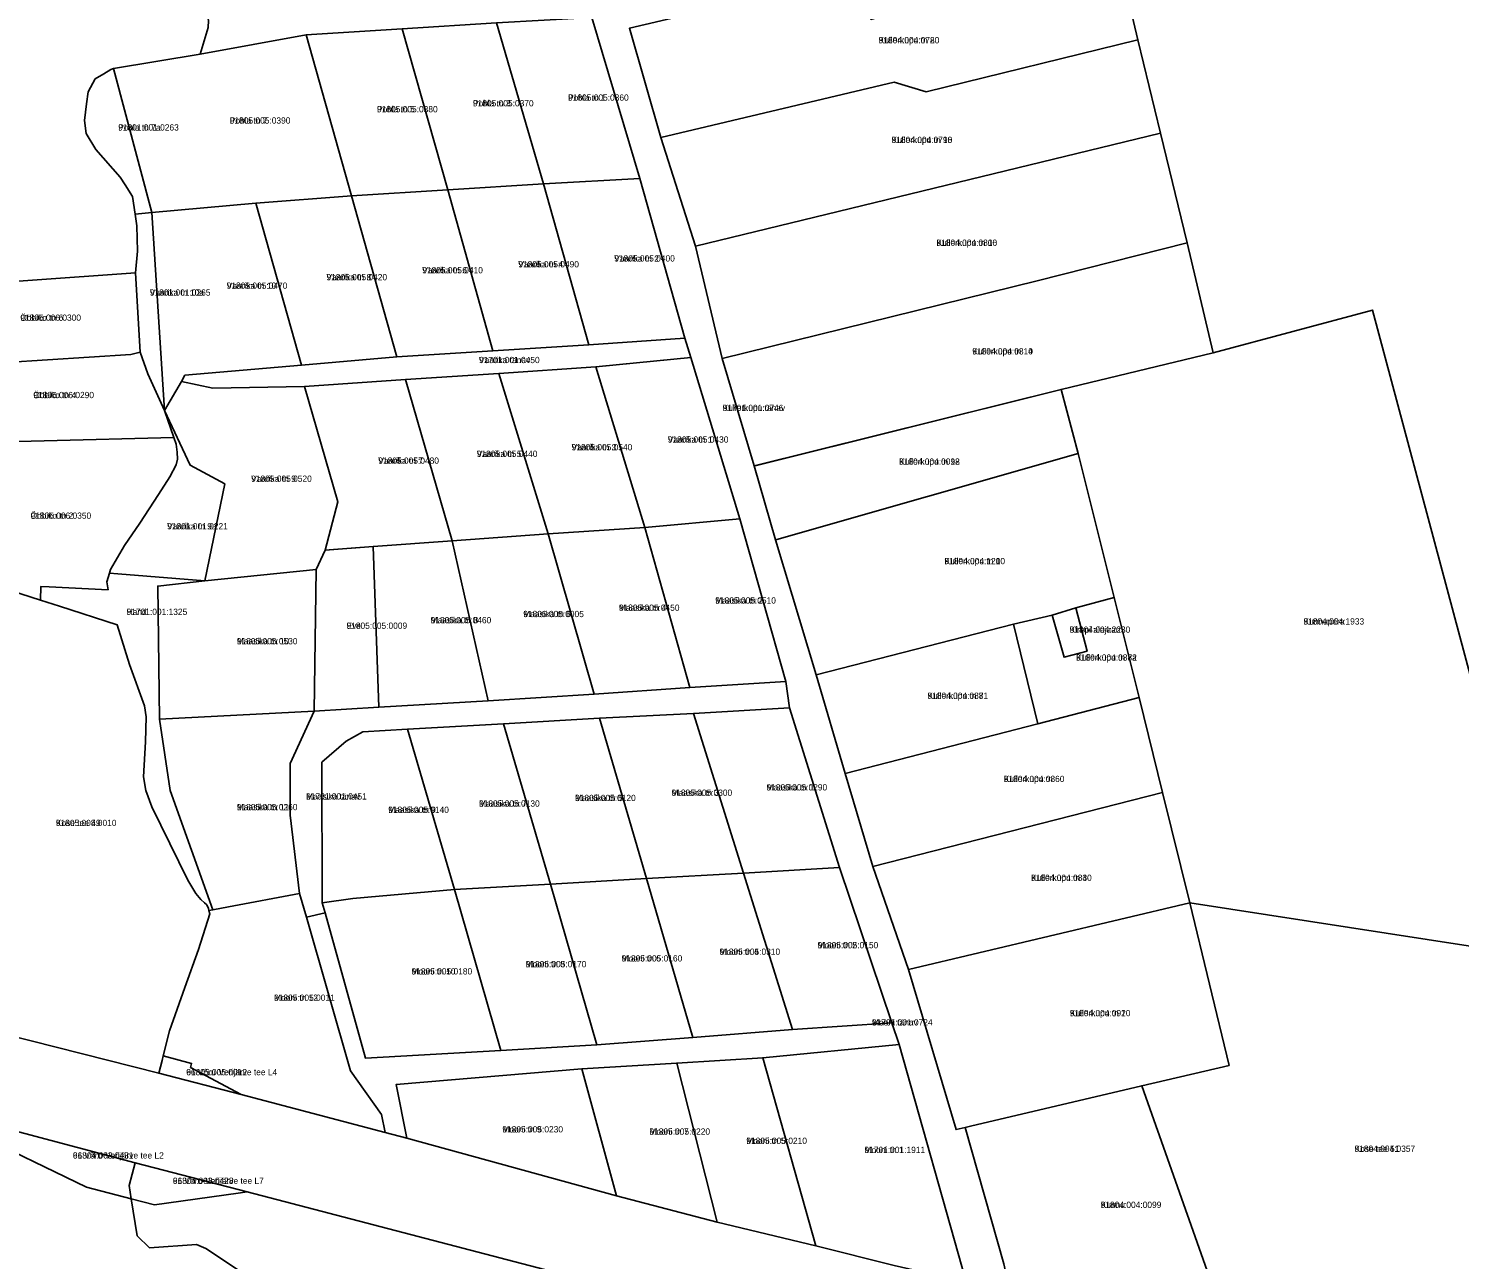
# Model space of a CAD drawing. Extents: x 655954 to 711923, y 6395079 to 6429745.
# Drawn here: x 680907.6 to 681249.8, y 6411990.7 to 6412285 of the extents above; entities that cross this region are included whole.
import ezdxf

# ---------------------------------------------------------------- set-up
doc = ezdxf.new("R2010")
doc.units = 0
for name, color, linetype in [('L_AADRESS', 7, 'Continuous'), ('PIIR', 7, 'Continuous'), ('TUNNUS', 7, 'Continuous')]:
    doc.layers.add(name, color=color, linetype=linetype)

msp = doc.modelspace()

# ---------------------------------------------------------------- linework, layer by layer
at = {"layer": 'PIIR'}
for points in [[(681328.62, 6412350.34), (681350.64, 6412272.52), (681360.54, 6412232.94), (681368.44, 6412234.18), (681393.19, 6412133.84), (681385.56, 6412131.89), (681365.57, 6412212.54), (681268.71, 6412187.17), (681303.76, 6412042.93), (681275.58, 6412043.52), (681270.46, 6412062.78), (681228.97, 6412217.72), (681190.9, 6412207.5), (681184.65, 6412233.77), (681178.3, 6412260), (681172.89, 6412282.37), (681167.77, 6412304.01), (681183.61, 6412308.53), (681212.34, 6412317.04), (681255.92, 6412329.46), (681298.51, 6412341.6)], [(681058.75, 6412259.04), (681051.29, 6412285.13), (681103.06, 6412297.32), (681106.19, 6412298.14), (681109.04, 6412287.26), (681152.34, 6412299.81), (681167.77, 6412304.01), (681172.89, 6412282.37), (681122.23, 6412269.96), (681114.62, 6412272.26)], [(681039.94, 6412294.61), (681042.3, 6412287.68), (681019.45, 6412286.4), (680996.96, 6412284.96), (680974, 6412283.59), (680948.65, 6412278.97), (680950.53, 6412285.32), (680950.61, 6412286.95), (680950.29, 6412288.38), (680961.57, 6412289.23), (680968.7, 6412289.64), (680994.18, 6412291.02), (681017.05, 6412292.76)], [(681007.81, 6412246.45), (680984.84, 6412245.09), (680974, 6412283.59), (680996.96, 6412284.96)], [(681030.76, 6412247.91), (681007.81, 6412246.45), (680996.96, 6412284.96), (681019.45, 6412286.4)], [(681019.45, 6412286.4), (681042.3, 6412287.68), (681053.74, 6412249.18), (681030.76, 6412247.91)], [(680984.84, 6412245.09), (680961.97, 6412243.26), (680937.1, 6412241.06), (680927.87, 6412275.54), (680948.65, 6412278.97), (680974, 6412283.59)], [(681067.08, 6412232.99), (681058.75, 6412259.04), (681114.62, 6412272.26), (681122.23, 6412269.96), (681172.89, 6412282.37), (681178.3, 6412260)], [(680927.26, 6412275.29), (680927.87, 6412275.54), (680937.1, 6412241.06), (680933.09, 6412240.65), (680932.44, 6412244.91), (680930.67, 6412247.65), (680929.48, 6412249.5), (680923.66, 6412256.12), (680921.34, 6412259.97), (680920.92, 6412263.06), (680921.43, 6412267.09), (680921.8, 6412269.94), (680923.52, 6412273.03), (680925.6, 6412274.21)], [(681073.48, 6412206.17), (681067.08, 6412232.99), (681178.3, 6412260), (681184.65, 6412233.77), (681148.79, 6412224.76)], [(681041.58, 6412209.41), (681018.62, 6412207.94), (681007.81, 6412246.45), (681030.76, 6412247.91)], [(681041.58, 6412209.41), (681030.76, 6412247.91), (681053.74, 6412249.18), (681064.52, 6412211)], [(680995.67, 6412206.56), (680972.84, 6412204.56), (680961.97, 6412243.26), (680984.84, 6412245.09)], [(681018.62, 6412207.94), (680995.67, 6412206.56), (680984.84, 6412245.09), (681007.81, 6412246.45)], [(680933.64, 6412231.78), (680933.44, 6412237.91), (680933.09, 6412240.65), (680937.1, 6412241.06), (680940.09, 6412193.73), (680936.09, 6412202.44), (680934.3, 6412207.68), (680933.18, 6412226.66)], [(680972.84, 6412204.56), (680944.99, 6412202.12), (680944.14, 6412200.66), (680940.09, 6412193.73), (680937.1, 6412241.06), (680961.97, 6412243.26)], [(681081.1, 6412180.44), (681073.48, 6412206.17), (681148.79, 6412224.76), (681184.65, 6412233.77), (681190.9, 6412207.5), (681154.51, 6412198.74)], [(680882.15, 6412203.95), (680877.77, 6412203.66), (680877.27, 6412218.69), (680877.37, 6412222.76), (680881.55, 6412222.94), (680933.18, 6412226.66), (680934.3, 6412207.68), (680932.05, 6412207.12)], [(681228.97, 6412217.72), (681270.46, 6412062.78), (681185.26, 6412075.96), (681178.74, 6412102.37), (681173.14, 6412125.06), (681167.22, 6412148.95), (681158.62, 6412183.44), (681154.51, 6412198.74), (681190.9, 6412207.5)], [(681064.52, 6412211), (681065.99, 6412206.38), (681048.93, 6412204.7), (681043.24, 6412204.15), (681020.01, 6412202.54), (680997.72, 6412201.12), (680973.58, 6412199.41), (680951.61, 6412199.07), (680944.14, 6412200.66), (680944.99, 6412202.12), (680972.84, 6412204.56), (680995.67, 6412206.56), (681018.62, 6412207.94), (681041.58, 6412209.41)], [(680942.34, 6412187.24), (680880.22, 6412185.64), (680877.77, 6412203.66), (680882.15, 6412203.95), (680932.05, 6412207.12), (680934.3, 6412207.68), (680936.09, 6412202.44), (680940.09, 6412193.73)], [(681043.24, 6412204.15), (681065.99, 6412206.38), (681077.65, 6412167.76), (681054.92, 6412165.71)], [(681020.01, 6412202.54), (681043.24, 6412204.15), (681054.92, 6412165.71), (681031.81, 6412164.23)], [(680944.14, 6412200.66), (680951.61, 6412199.07), (680973.58, 6412199.41), (680981.52, 6412171.83), (680978.48, 6412160.3), (680976.39, 6412155.67), (680949.72, 6412152.96), (680954.53, 6412176.14), (680946.26, 6412180.63), (680940.09, 6412193.73)], [(681008.87, 6412162.56), (680989.99, 6412161.18), (680978.48, 6412160.3), (680981.52, 6412171.83), (680973.58, 6412199.41), (680997.72, 6412201.12)], [(680997.72, 6412201.12), (681020.01, 6412202.54), (681031.81, 6412164.23), (681008.87, 6412162.56)], [(681081.1, 6412180.44), (681081.32, 6412180.49), (681154.51, 6412198.74), (681158.62, 6412183.44), (681086.49, 6412162.83), (681086.23, 6412162.75)], [(680942.34, 6412187.24), (680940.09, 6412193.73), (680946.26, 6412180.63), (680954.53, 6412176.14), (680949.72, 6412152.96), (680928.93, 6412154.66), (680926.93, 6412154.82), (680927.17, 6412155.65), (680930.54, 6412161.41), (680934.19, 6412166.77), (680938.65, 6412173.58), (680941.35, 6412177.83), (680942.89, 6412180.73), (680943.17, 6412182.04), (680943.13, 6412183.74), (680942.89, 6412185.65)], [(680910.4, 6412148.38), (680894.01, 6412153.62), (680883.54, 6412157.28), (680881.81, 6412157.84), (680881.12, 6412169.9), (680880.22, 6412185.64), (680942.34, 6412187.24), (680942.89, 6412185.65), (680943.13, 6412183.74), (680943.17, 6412182.04), (680942.89, 6412180.73), (680941.35, 6412177.83), (680938.65, 6412173.58), (680934.19, 6412166.77), (680930.54, 6412161.41), (680927.17, 6412155.65), (680926.93, 6412154.82), (680926.32, 6412152.73), (680926.58, 6412150.84), (680912.52, 6412151.51), (680910.54, 6412151.62)], [(681086.49, 6412162.83), (681158.62, 6412183.44), (681167.22, 6412148.95), (681158, 6412146.52), (681152.37, 6412144.73), (681143.13, 6412142.58), (681095.94, 6412130.45), (681086.23, 6412162.75)], [(681065.69, 6412127.46), (681042.88, 6412125.88), (681031.81, 6412164.23), (681054.92, 6412165.71)], [(681088.67, 6412128.86), (681065.69, 6412127.46), (681054.92, 6412165.71), (681077.65, 6412167.76)], [(680991.31, 6412122.77), (680989.99, 6412161.18), (681008.87, 6412162.56), (681017.47, 6412124.23)], [(681031.81, 6412164.23), (681042.88, 6412125.88), (681017.47, 6412124.23), (681008.87, 6412162.56)], [(680978.48, 6412160.3), (680979.48, 6412160.38), (680989.99, 6412161.18), (680991.31, 6412122.77), (680975.92, 6412121.81), (680976.39, 6412155.67)], [(680938.87, 6412119.9), (680938.46, 6412151.7), (680949.72, 6412152.96), (680976.39, 6412155.67), (680975.92, 6412121.81)], [(680931.7, 6412132.96), (680928.8, 6412142.45), (680914.95, 6412146.88), (680910.4, 6412148.38), (680910.54, 6412151.62), (680912.52, 6412151.51), (680926.58, 6412150.84), (680926.32, 6412152.73), (680926.93, 6412154.82), (680928.93, 6412154.66), (680949.72, 6412152.96), (680938.46, 6412151.7), (680938.87, 6412119.9), (680941.47, 6412102.8), (680951.66, 6412074.3), (680950.73, 6412074.13), (680950.63, 6412074.59), (680950.21, 6412075.5), (680949.63, 6412075.95), (680948.79, 6412076.76), (680947.55, 6412078.19), (680945.64, 6412081.4), (680937.07, 6412098.88), (680935.59, 6412102.84), (680935.06, 6412106.12), (680935.53, 6412114.43), (680935.74, 6412120.41), (680935.31, 6412123.11)], [(681143.13, 6412142.58), (681152.37, 6412144.73), (681155.2, 6412134.7), (681160.73, 6412136.11), (681158, 6412146.52), (681167.22, 6412148.95), (681173.14, 6412125.06), (681148.93, 6412118.8)], [(681152.37, 6412144.73), (681158, 6412146.52), (681160.73, 6412136.11), (681155.2, 6412134.7)], [(681095.94, 6412130.45), (681143.13, 6412142.58), (681148.93, 6412118.8), (681102.86, 6412106.91)], [(681089.56, 6412122.59), (681066.6, 6412121.25), (681044.13, 6412120.16), (681021.17, 6412118.8), (680998.21, 6412117.5), (680987.53, 6412116.85), (680983.57, 6412114.63), (680977.73, 6412109.59), (680977.83, 6412075.97), (680978.52, 6412073.53), (680974.02, 6412072.49), (680972.4, 6412078.16), (680970.18, 6412096.94), (680970.12, 6412109.25), (680975.92, 6412121.81), (680991.31, 6412122.77), (681017.47, 6412124.23), (681042.88, 6412125.88), (681065.69, 6412127.46), (681088.67, 6412128.86)], [(681109.51, 6412084.62), (681102.86, 6412106.91), (681148.93, 6412118.8), (681173.14, 6412125.06), (681178.74, 6412102.37)], [(680951.66, 6412074.3), (680941.47, 6412102.8), (680938.87, 6412119.9), (680975.92, 6412121.81), (680970.12, 6412109.25), (680970.18, 6412096.94), (680972.4, 6412078.16), (680955.37, 6412074.98)], [(681055.39, 6412081.78), (681044.13, 6412120.16), (681066.6, 6412121.25), (681078.56, 6412083.08)], [(681078.56, 6412083.08), (681066.6, 6412121.25), (681089.56, 6412122.59), (681101.52, 6412084.42)], [(680977.83, 6412075.97), (680977.73, 6412109.59), (680983.57, 6412114.63), (680987.53, 6412116.85), (680998.21, 6412117.5), (681009.47, 6412079.12), (680985.16, 6412076.98)], [(681009.47, 6412079.12), (680998.21, 6412117.5), (681021.17, 6412118.8), (681032.43, 6412080.42)], [(681032.43, 6412080.42), (681021.17, 6412118.8), (681044.13, 6412120.16), (681055.39, 6412081.78)], [(681178.74, 6412102.37), (681185.26, 6412075.96), (681118.02, 6412060.02), (681109.51, 6412084.62)], [(681066.4, 6412043.78), (681055.39, 6412081.78), (681078.56, 6412083.08), (681090.24, 6412045.67)], [(681090.24, 6412045.67), (681078.56, 6412083.08), (681101.52, 6412084.42), (681113.99, 6412047.26)], [(681020.51, 6412040.67), (681009.47, 6412079.12), (681032.43, 6412080.42), (681043.47, 6412041.97)], [(681043.47, 6412041.97), (681032.43, 6412080.42), (681055.39, 6412081.78), (681066.4, 6412043.78)], [(680972.4, 6412078.16), (680974.02, 6412072.49), (680984.54, 6412035.81), (680992.01, 6412025.32), (680992.85, 6412021.05), (680958.41, 6412030.09), (680946.31, 6412036.59), (680946.56, 6412037.56), (680939.76, 6412039.33), (680941.26, 6412045.35), (680944.93, 6412055.71), (680948.26, 6412064.8), (680950.9, 6412073.35), (680950.73, 6412074.13), (680951.66, 6412074.3), (680955.37, 6412074.98)], [(680988.17, 6412038.78), (680978.52, 6412073.53), (680977.83, 6412075.97), (680985.16, 6412076.98), (681009.47, 6412079.12), (681020.51, 6412040.67)], [(681115.76, 6412042.05), (681083.17, 6412038.92), (681062.61, 6412037.63), (681039.89, 6412036.23), (680995.49, 6412032.47), (680998.02, 6412019.7), (680992.85, 6412021.05), (680992.01, 6412025.32), (680984.54, 6412035.81), (680974.02, 6412072.49), (680978.52, 6412073.53), (680988.17, 6412038.78), (681020.51, 6412040.67), (681043.47, 6412041.97), (681066.4, 6412043.78), (681090.24, 6412045.67), (681113.99, 6412047.26)], [(681194.69, 6412037.06), (681173.78, 6412032.2), (681132.84, 6412022.54), (681131.58, 6412022.24), (681129.38, 6412021.71), (681118.02, 6412060.02), (681185.26, 6412075.96)], [(681185.26, 6412075.96), (681270.46, 6412062.78), (681275.58, 6412043.52), (681265.16, 6412003.98), (681252.39, 6411955.69), (681195.56, 6411970.54), (681173.78, 6412032.2), (681194.69, 6412037.06)], [(681095.85, 6411993.91), (681083.17, 6412038.92), (681115.76, 6412042.05), (681131.81, 6411985.29), (681114.62, 6411989.2)], [(680939.76, 6412039.33), (680946.56, 6412037.56), (680946.31, 6412036.59), (680958.41, 6412030.09), (680938.72, 6412035.25), (680939.5, 6412038.28)], [(681095.85, 6411993.91), (681072.23, 6411999.62), (681062.61, 6412037.63), (681083.17, 6412038.92)], [(681048.15, 6412005.85), (680998.02, 6412019.7), (680995.49, 6412032.47), (681039.89, 6412036.23)], [(681072.23, 6411999.62), (681048.15, 6412005.85), (681039.89, 6412036.23), (681062.61, 6412037.63)], [(681131.58, 6412022.24), (681132.84, 6412022.54), (681173.78, 6412032.2), (681195.56, 6411970.54), (681196.38, 6411968), (681142.64, 6411981.4), (681140.83, 6411989.59)], [(680892.85, 6412024.44), (680933.06, 6412013.75), (680931.64, 6412008.37), (680932.14, 6412005.16), (680921.45, 6412007.92), (680893.69, 6412021.37)], [(680933.06, 6412013.75), (680959.83, 6412006.81), (680957.7, 6412006.51), (680937.72, 6412003.7), (680932.14, 6412005.16), (680931.64, 6412008.37)]]:
    msp.add_lwpolyline(points, close=True, dxfattribs=at)
for points in [[(680950.53, 6412285.32), (680948.65, 6412278.97), (680927.87, 6412275.54), (680927.26, 6412275.29), (680925.6, 6412274.21), (680923.52, 6412273.03), (680921.8, 6412269.94), (680921.43, 6412267.09), (680920.92, 6412263.06), (680921.34, 6412259.97), (680923.66, 6412256.12), (680929.48, 6412249.5), (680930.67, 6412247.65), (680932.44, 6412244.91), (680933.09, 6412240.65), (680933.44, 6412237.91), (680933.64, 6412231.78), (680933.18, 6412226.66), (680881.55, 6412222.94)], [(681131.81, 6411985.29), (681115.76, 6412042.05), (681113.99, 6412047.26), (681101.52, 6412084.42), (681089.56, 6412122.59), (681088.67, 6412128.86), (681077.65, 6412167.76), (681065.99, 6412206.38), (681064.52, 6412211), (681053.74, 6412249.18), (681042.3, 6412287.68)], [(681051.29, 6412285.13), (681058.75, 6412259.04), (681067.08, 6412232.99), (681073.48, 6412206.17), (681081.1, 6412180.44), (681086.23, 6412162.75), (681095.94, 6412130.45), (681102.86, 6412106.91), (681109.51, 6412084.62), (681118.02, 6412060.02), (681129.38, 6412021.71), (681131.58, 6412022.24), (681140.83, 6411989.59)], [(680894.01, 6412153.62), (680910.4, 6412148.38), (680914.95, 6412146.88), (680928.8, 6412142.45), (680931.7, 6412132.96), (680935.31, 6412123.11), (680935.74, 6412120.41), (680935.53, 6412114.43), (680935.06, 6412106.12), (680935.59, 6412102.84), (680937.07, 6412098.88), (680945.64, 6412081.4), (680947.55, 6412078.19), (680948.79, 6412076.76), (680949.63, 6412075.95), (680950.21, 6412075.5), (680950.63, 6412074.59), (680950.73, 6412074.13), (680950.9, 6412073.35), (680948.26, 6412064.8), (680944.93, 6412055.71), (680941.26, 6412045.35), (680939.76, 6412039.33), (680939.5, 6412038.28), (680938.72, 6412035.25), (680877.31, 6412050.78)], [(680672.88, 6412104.96), (680691.94, 6412100.04), (680713.61, 6412094.57), (680712.89, 6412092.18), (680748.53, 6412082.52), (680786.53, 6412072.49), (680788.99, 6412071.84), (680834.37, 6412060.69), (680877.19, 6412049.18), (680877.31, 6412050.78), (680938.72, 6412035.25), (680958.41, 6412030.09), (680992.85, 6412021.05), (680998.02, 6412019.7), (681048.15, 6412005.85), (681072.23, 6411999.62), (681095.85, 6411993.91), (681114.62, 6411989.2), (681131.81, 6411985.29), (681142.64, 6411981.4), (681196.38, 6411968), (681251.89, 6411953.79)], [(681715.24, 6411810.02), (681453.34, 6411877.71), (681294.84, 6411919.24), (681247.61, 6411931.95), (681196.28, 6411945.45), (681144.95, 6411958.58), (681138, 6411960.36), (681067.39, 6411978.82), (681030.99, 6411988.27), (680959.83, 6412006.81), (680933.06, 6412013.75), (680892.85, 6412024.44), (680882.14, 6412027.25), (680877.44, 6412028.49), (680872.22, 6412029.86), (680856.28, 6412034.04), (680827.85, 6412041.39), (680779.17, 6412054.12), (680705.81, 6412074.78), (680677.03, 6412081.28)], [(680905.86, 6411977.12), (680893.69, 6412021.37), (680921.45, 6412007.92), (680932.14, 6412005.16), (680933.52, 6411996.33), (680936.54, 6411993.46), (680947.76, 6411994.27), (680949.96, 6411993.29), (680959.44, 6411986.97)], [(680959.44, 6411986.97), (680949.96, 6411993.29), (680947.76, 6411994.27), (680936.54, 6411993.46), (680933.52, 6411996.33), (680932.14, 6412005.16), (680937.72, 6412003.7), (680957.7, 6412006.51), (680959.83, 6412006.81), (681030.99, 6411988.27)]]:
    msp.add_lwpolyline(points, dxfattribs=at)

# ---------------------------------------------------------------- texts
at = {"layer": 'L_AADRESS'}
for s, p in [('Kullerkupu tn 20', (681110.88, 6412281.53)), ('Pohla tn 3', (681013.86, 6412266.44)), ('Pohla tn 1', (681036.6, 6412267.8)), ('Pohla tn 5', (680990.91, 6412265.02)), ('Pohla tn 7a', (680929.01, 6412260.66)), ('Pohla tn 7', (680955.7, 6412262.32)), ('Kullerkupu tn 18', (681113.97, 6412257.68)), ('Kullerkupu tn 16', (681124.7, 6412233.09)), ('Vaarika tn 2', (681047.64, 6412229.34)), ('Vaarika tn 6', (681001.73, 6412226.51)), ('Vaarika tn 4', (681024.7, 6412227.93)), ('Vaarika tn 10', (680954.97, 6412222.82)), ('Vaarika tn 8', (680978.82, 6412224.85)), ('Vaarika tn 10a', (680936.59, 6412221.18)), ('Ööbiku tn 6', (680905.62, 6412215.16)), ('Vaarika tänav', (681015.3, 6412205.04)), ('Kullerkupu tn 14', (681133.26, 6412207.11)), ('Ööbiku tn 4', (680908.73, 6412196.66)), ('Kullerkupu tänav', (681073.57, 6412193.57)), ('Vaarika tn 3', (681037.46, 6412184.17)), ('Vaarika tn 1', (681060.45, 6412186.02)), ('Vaarika tn 7', (680991.22, 6412180.97)), ('Vaarika tn 5', (681014.77, 6412182.6)), ('Kullerkupu tn 12', (681115.77, 6412180.74)), ('Vaarika tn 9', (680960.81, 6412176.65)), ('Ööbiku tn 2', (680908.06, 6412167.81)), ('Vaarika tn 9a', (680940.73, 6412165.27)), ('Kullerkupu tn 10', (681126.6, 6412156.95)), ('Maasika tn 2', (681071.8, 6412147.53)), ('Handi', (680931.03, 6412144.82)), ('Maasika tn 6', (681025.88, 6412144.29)), ('Maasika tn 4', (681048.75, 6412145.8)), ('Eve', (680983.62, 6412141.49)), ('Maasika tn 8', (681003.73, 6412142.82)), ('Kirepi alajaam', (681156.55, 6412140.55)), ('Kunnupera', (681212.48, 6412142.52)), ('Maasika tn 10', (680957.39, 6412137.79)), ('Kullerkupu tn 8a', (681158.1, 6412133.88)), ('Kullerkupu tn 8', (681122.55, 6412124.74)), ('Maasika tn 1', (681084.06, 6412102.83)), ('Kullerkupu tn 6', (681140.8, 6412104.84)), ('Maasika tänav', (680973.96, 6412100.67)), ('Maasika tn 7', (681015.32, 6412098.96)), ('Maasika tn 5', (681038.28, 6412100.29)), ('Maasika tn 3', (681061.35, 6412101.55)), ('Maasika tn 11', (680957.39, 6412098.11)), ('Maasika tn 9', (680993.6, 6412097.47)), ('Kose tee 49', (680914.11, 6412094.32)), ('Kullerkupu tn 4', (681147.33, 6412081.2)), ('Mooni tn 2', (681096.28, 6412065.09)), ('Mooni tn 6', (681049.41, 6412061.93)), ('Mooni tn 4', (681072.82, 6412063.52)), ('Mooni tn 10', (680999.17, 6412058.82)), ('Mooni tn 8', (681026.47, 6412060.55)), ('Mooni tn 12', (680966.3, 6412052.52)), ('Kullerkupu tn 2', (681156.59, 6412048.84)), ('Mooni tänav', (681109.28, 6412046.62)), ('66 Võru-Verijärve tee L4', (680945.3, 6412034.71)), ('Mooni tn 9', (681020.89, 6412021.04)), ('Mooni tn 7', (681056.06, 6412020.51)), ('Mooni tn 5', (681079.23, 6412018.3)), ('66 Võru-Verijärve tee L2', (680918.18, 6412014.8)), ('Mooni tn 1', (681107.49, 6412016.12)), ('Kose tee 51', (681224.68, 6412016.4)), ('66 Võru-Verijärve tee L7', (680942.09, 6412008.73)), ('Kunnu', (681163.98, 6412002.98))]:
    msp.add_text(s, height=1.5, dxfattribs=at).set_placement(p)
at = {"layer": 'TUNNUS'}
for s, p in [('91804:004:0780', (681110.88, 6412281.53)), ('91805:005:0370', (681013.86, 6412266.44)), ('91805:005:0360', (681036.6, 6412267.8)), ('91805:005:0380', (680990.91, 6412265.02)), ('91801:001:0263', (680929.01, 6412260.66)), ('91805:005:0390', (680955.7, 6412262.32)), ('91804:004:0790', (681113.97, 6412257.68)), ('91804:004:0800', (681124.7, 6412233.09)), ('91805:005:0400', (681047.64, 6412229.34)), ('91805:005:0410', (681001.73, 6412226.51)), ('91805:005:0490', (681024.7, 6412227.93)), ('91805:005:0470', (680954.97, 6412222.82)), ('91805:005:0420', (680978.82, 6412224.85)), ('91801:001:0265', (680936.59, 6412221.18)), ('91805:006:0300', (680905.62, 6412215.16)), ('91701:001:0450', (681015.3, 6412205.04)), ('91804:004:0810', (681133.26, 6412207.11)), ('91805:006:0290', (680908.73, 6412196.66)), ('91701:001:0746', (681073.57, 6412193.57)), ('91805:005:0540', (681037.46, 6412184.17)), ('91805:005:0430', (681060.45, 6412186.02)), ('91805:005:0480', (680991.22, 6412180.97)), ('91805:005:0440', (681014.77, 6412182.6)), ('91804:004:0098', (681115.77, 6412180.74)), ('91805:005:0520', (680960.81, 6412176.65)), ('91805:006:0350', (680908.06, 6412167.81)), ('91801:001:0221', (680940.73, 6412165.27)), ('91804:004:1200', (681126.6, 6412156.95)), ('91805:005:0510', (681071.8, 6412147.53)), ('91701:001:1325', (680931.03, 6412144.82)), ('91805:005:0005', (681025.88, 6412144.29)), ('91805:005:0450', (681048.75, 6412145.8)), ('91805:005:0009', (680983.62, 6412141.49)), ('91805:005:0460', (681003.73, 6412142.82)), ('91804:004:2230', (681156.55, 6412140.55)), ('91804:004:1933', (681212.48, 6412142.52)), ('91805:005:0530', (680957.39, 6412137.79)), ('91804:004:0872', (681158.1, 6412133.88)), ('91804:004:0871', (681122.55, 6412124.74)), ('91805:005:0290', (681084.06, 6412102.83)), ('91804:004:0860', (681140.8, 6412104.84)), ('91701:001:0451', (680973.96, 6412100.67)), ('91805:005:0130', (681015.32, 6412098.96)), ('91805:005:0120', (681038.28, 6412100.29)), ('91805:005:0300', (681061.35, 6412101.55)), ('91805:005:0260', (680957.39, 6412098.11)), ('91805:005:0140', (680993.6, 6412097.47)), ('91805:008:0010', (680914.11, 6412094.32)), ('91804:004:0830', (681147.33, 6412081.2)), ('91805:005:0150', (681096.28, 6412065.09)), ('91805:005:0160', (681049.41, 6412061.93)), ('91805:005:0310', (681072.82, 6412063.52)), ('91805:005:0180', (680999.17, 6412058.82)), ('91805:005:0170', (681026.47, 6412060.55)), ('91805:005:0011', (680966.3, 6412052.52)), ('91804:004:0910', (681156.59, 6412048.84)), ('91701:001:0724', (681109.28, 6412046.62)), ('91805:005:0012', (680945.3, 6412034.71)), ('91805:005:0230', (681020.89, 6412021.04)), ('91805:005:0220', (681056.06, 6412020.51)), ('91805:005:0210', (681079.23, 6412018.3)), ('91804:003:0431', (680918.18, 6412014.8)), ('91701:001:1911', (681107.49, 6412016.12)), ('91804:004:0357', (681224.68, 6412016.4)), ('91804:003:0428', (680942.09, 6412008.73)), ('91804:004:0099', (681163.98, 6412002.98))]:
    msp.add_text(s, height=1.5, dxfattribs=at).set_placement(p)

doc.saveas('drawing.dxf')
